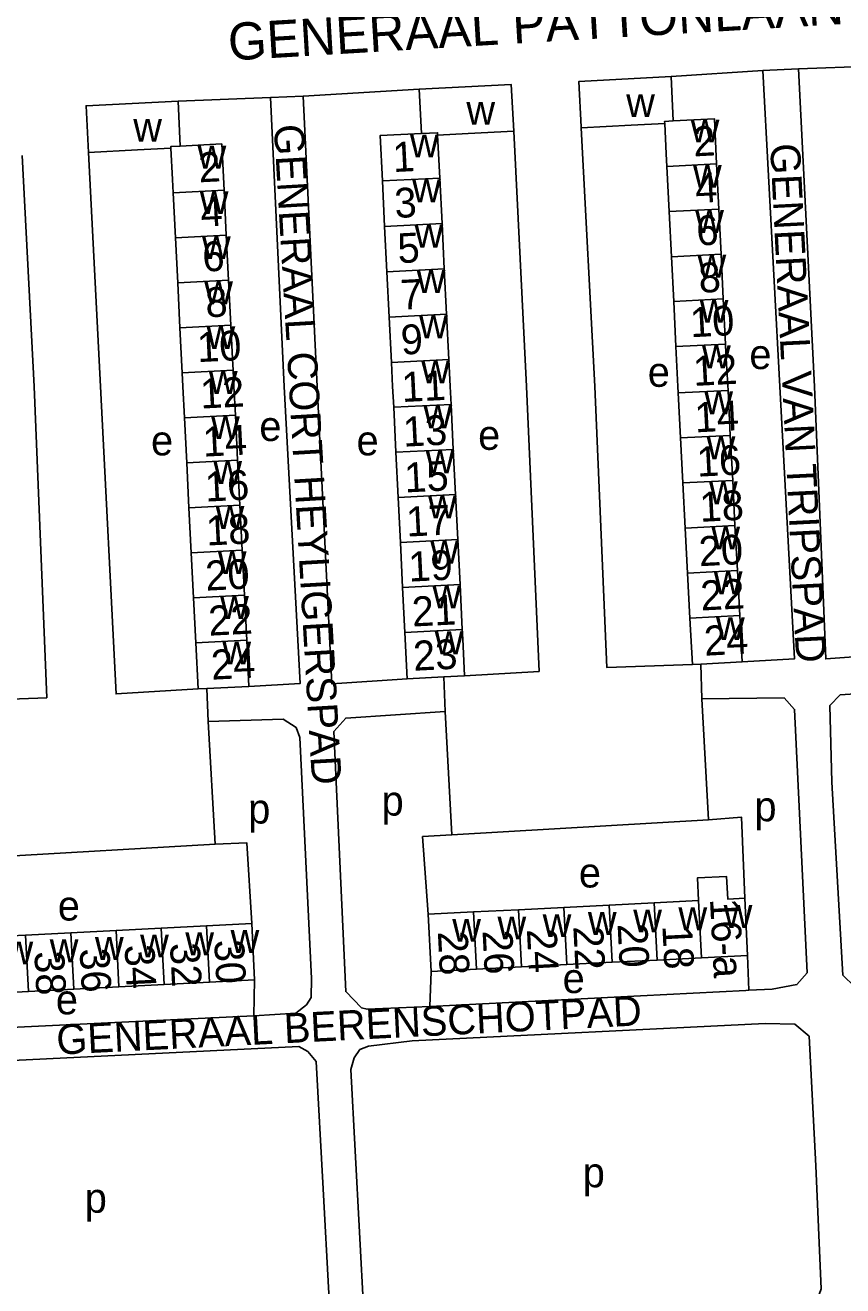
# Model space of a CAD drawing. Extents: x 159294 to 161936, y 384538 to 386517.
# Drawn here: x 161388.8 to 161498.7, y 385579.2 to 385748.5 of the extents above; entities that cross this region are included whole.
import ezdxf

# ---------------------------------------------------------------- set-up
doc = ezdxf.new("R2010")
doc.units = 0
for name, color, linetype in [('BLT_Basislijn', 7, 'Continuous'), ('BLT_Bebouwing', 7, 'Continuous'), ('BLT_Centroide', 7, 'Continuous'), ('BLT_Huisnummer', 7, 'Continuous'), ('BLT_Huisnummer_ tussenligend', 7, 'Continuous'), ('BLT_Huisnummer_reeks', 7, 'Continuous'), ('BLT_Onderverdeling_panden', 7, 'Continuous'), ('BLT_Straatnaam', 7, 'Continuous'), ('BLT_Straatnaam_verkleind', 7, 'Continuous')]:
    doc.layers.add(name, color=color, linetype=linetype)

msp = doc.modelspace()

# ---------------------------------------------------------------- linework, layer by layer
at = {"layer": 'BLT_Basislijn'}
for p, q in [((161475.6, 385741.64), (161487.92, 385742.47)), ((161487.92, 385742.47), (161492.75, 385742.69)), ((161508.06, 385743.25), (161492.75, 385742.69)), ((161409.33, 385738.32), (161421.78, 385738.84)), ((161426.15, 385739.02), (161421.78, 385738.84)), ((161426.15, 385739.02), (161441.74, 385739.94)), ((161479.59, 385662.72), (161479.74, 385658.06)), ((161445.23, 385656.36), (161445.06, 385660.98)), ((161413.19, 385659.43), (161413.4, 385654.98)), ((161480.63, 385641.78), (161479.74, 385658.06)), ((161446.14, 385639.77), (161445.23, 385656.36)), ((161413.4, 385654.98), (161414.31, 385638.51)), ((161480.63, 385641.78), (161446.14, 385639.77)), ((161414.31, 385638.51), (161380.08, 385636.52)), ((161486.08, 385618.9), (161485.9, 385623.58)), ((161419.53, 385615.47), (161419.62, 385620.28)), ((161443.18, 385616.7), (161443.35, 385621.41)), ((161377.03, 385613.45), (161419.53, 385615.47))]:
    msp.add_line(p, q, dxfattribs=at)
for points in [[(161485.15, 385663.01), (161492.21, 385663.42), (161490.21, 385700), (161487.92, 385742.47)], [(161506.47, 385664.15), (161496.4, 385663.41), (161494.88, 385700), (161492.75, 385742.69)], [(161418.87, 385659.71), (161425.77, 385660.11), (161423.59, 385700), (161421.78, 385738.84)], [(161440.13, 385660.74), (161430.01, 385660.06), (161428.03, 385700), (161426.15, 385739.02)], [(161454.45, 385734.29), (161456.16, 385700), (161457.86, 385661.73), (161447.85, 385661.12)], [(161478.47, 385662.66), (161466.97, 385662.26), (161465.37, 385700), (161463.53, 385734.75)], [(161388.36, 385731.02), (161389.99, 385700), (161391.68, 385658.18), (161381.85, 385657.81)], [(161412.02, 385659.37), (161401, 385658.7), (161398.91, 385700), (161397.29, 385731.45)], [(161511.65, 385659.49), (161498.34, 385658.6), (161496.96, 385657.17), (161497.23, 385646.85), (161498.69, 385620.93), (161500.25, 385619.42), (161509.83, 385619.75)], [(161486.08, 385618.9), (161489.18, 385619.04), (161492.52, 385619.67), (161493.89, 385621.26), (161492.2, 385656.63), (161490.8, 385658.16), (161479.74, 385658.06)], [(161443.18, 385616.7), (161434.74, 385616.34), (161434, 385616.54), (161431.87, 385618.72), (161430.28, 385653.64), (161431.87, 385655.45), (161445.23, 385656.36)], [(161419.53, 385615.47), (161425.18, 385615.83), (161426.59, 385616.95), (161427.21, 385617.93), (161427.29, 385620.46), (161425.7, 385652.86), (161425.2, 385654.18), (161423.45, 385655.33), (161413.4, 385654.98)], [(161480.63, 385641.78), (161485.09, 385642.14), (161485.51, 385631.27)], [(161446.14, 385639.77), (161442.21, 385639.55), (161442.95, 385629.1)], [(161414.31, 385638.51), (161418.58, 385638.68), (161419.23, 385627.86)], [(161443.18, 385616.7), (161485.67, 385618.88), (161486.08, 385618.9)], [(161495.05, 385595.31), (161494.15, 385612.73), (161492.26, 385614.34), (161488.24, 385614.45), (161440.82, 385612.09), (161434.95, 385611.37), (161433.78, 385610.93), (161432.99, 385609.82), (161432.55, 385608.26), (161434.3, 385575.49), (161434.94, 385574.37), (161436.21, 385573.48), (161493.97, 385576.39), (161495.52, 385578.01), (161495.8, 385578.78), (161495.05, 385595.31)], [(161428.83, 385592.2), (161427.9, 385609.34), (161426.77, 385610.66), (161425.58, 385611.32), (161369.6, 385608.62), (161367.69, 385607.65), (161366.84, 385606.32), (161366.55, 385602.63), (161368.13, 385572.42), (161369.7, 385570.54), (161370.4, 385570.36), (161426.69, 385573.21), (161427.74, 385573.5), (161429.49, 385575.37), (161429.6, 385578.17), (161428.83, 385592.2)]]:
    msp.add_lwpolyline(points, dxfattribs=at)
at = {"layer": 'BLT_Bebouwing'}
for p, q in [((161475.6, 385741.64), (161475.91, 385735.68)), ((161441.74, 385739.94), (161442.04, 385733.97)), ((161409.33, 385738.32), (161409.63, 385732.3)), ((161444.51, 385727.99), (161444.23, 385733.78)), ((161475.36, 385723.49), (161475.05, 385729.57)), ((161481.73, 385729.92), (161482.04, 385723.83)), ((161436.8, 385727.61), (161437.1, 385721.51)), ((161444.82, 385721.9), (161444.51, 385727.99)), ((161415.52, 385726.36), (161415.82, 385720.32)), ((161482.04, 385723.83), (161482.34, 385717.79)), ((161445.12, 385715.81), (161444.82, 385721.9)), ((161475.66, 385717.44), (161475.36, 385723.49)), ((161415.82, 385720.32), (161416.12, 385714.27)), ((161437.1, 385721.51), (161437.41, 385715.42)), ((161409.29, 385713.93), (161408.98, 385719.97)), ((161475.96, 385711.44), (161475.66, 385717.44)), ((161482.34, 385717.79), (161482.63, 385711.79)), ((161437.41, 385715.42), (161437.71, 385709.33)), ((161445.43, 385709.71), (161445.12, 385715.81)), ((161409.59, 385707.88), (161409.29, 385713.93)), ((161416.12, 385714.27), (161416.43, 385708.23)), ((161482.63, 385711.79), (161482.93, 385705.71)), ((161476.26, 385705.36), (161475.96, 385711.44)), ((161437.71, 385709.33), (161438.02, 385703.24)), ((161445.73, 385703.62), (161445.43, 385709.71)), ((161409.9, 385701.84), (161409.59, 385707.88)), ((161476.89, 385693.09), (161476.57, 385699.14)), ((161483.26, 385699.48), (161483.57, 385693.43)), ((161438.32, 385697.22), (161438.62, 385691.17)), ((161446.33, 385691.55), (161446.03, 385697.6)), ((161410.5, 385689.75), (161410.2, 385695.8)), ((161417.04, 385696.14), (161417.34, 385690.1)), ((161477.2, 385687.04), (161476.89, 385693.09)), ((161483.57, 385693.43), (161483.89, 385687.38)), ((161446.63, 385685.5), (161446.33, 385691.55)), ((161410.8, 385683.71), (161410.5, 385689.75)), ((161417.34, 385690.1), (161417.65, 385684.06)), ((161438.62, 385691.17), (161438.92, 385685.11)), ((161477.52, 385680.99), (161477.2, 385687.04)), ((161483.89, 385687.38), (161484.2, 385681.33)), ((161438.92, 385685.11), (161439.22, 385679.06)), ((161446.93, 385679.45), (161446.63, 385685.5)), ((161411.1, 385677.67), (161410.8, 385683.71)), ((161417.65, 385684.06), (161417.95, 385678.01)), ((161484.2, 385681.33), (161484.52, 385675.28)), ((161477.83, 385674.94), (161477.52, 385680.99)), ((161417.95, 385678.01), (161418.26, 385671.97)), ((161439.22, 385679.06), (161439.52, 385673.01)), ((161447.24, 385673.4), (161446.93, 385679.45)), ((161411.4, 385671.62), (161411.1, 385677.67)), ((161478.14, 385668.89), (161477.83, 385674.94)), ((161484.52, 385675.28), (161484.83, 385669.23)), ((161439.52, 385673.01), (161439.82, 385666.96)), ((161447.54, 385667.34), (161447.24, 385673.4)), ((161411.71, 385665.58), (161411.4, 385671.62)), ((161418.26, 385671.97), (161418.56, 385665.93)), ((161478.47, 385662.66), (161478.14, 385668.89)), ((161484.83, 385669.23), (161485.15, 385663.01)), ((161418.56, 385665.93), (161418.87, 385659.71)), ((161439.82, 385666.96), (161440.13, 385660.74)), ((161412.02, 385659.37), (161411.71, 385665.58)), ((161479.59, 385662.72), (161478.47, 385662.66)), ((161485.15, 385663.01), (161479.59, 385662.72)), ((161440.13, 385660.74), (161445.06, 385660.98)), ((161445.06, 385660.98), (161447.85, 385661.12)), ((161413.19, 385659.43), (161412.02, 385659.37)), ((161418.87, 385659.71), (161413.19, 385659.43)), ((161473.35, 385630.65), (161467.27, 385630.34)), ((161479.31, 385630.95), (161473.35, 385630.65)), ((161485.9, 385623.58), (161485.51, 385631.27)), ((161449.03, 385629.41), (161442.95, 385629.1)), ((161442.95, 385629.1), (161443.35, 385621.41)), ((161455.11, 385629.72), (161449.03, 385629.41)), ((161461.19, 385630.03), (161455.11, 385629.72)), ((161467.27, 385630.34), (161461.19, 385630.03)), ((161407.08, 385627.24), (161401, 385626.93)), ((161413.16, 385627.55), (161407.08, 385627.24)), ((161419.23, 385627.86), (161413.16, 385627.55)), ((161419.62, 385620.28), (161419.23, 385627.86)), ((161388.85, 385626.3), (161382.77, 385625.99)), ((161394.93, 385626.61), (161388.85, 385626.3)), ((161401, 385626.93), (161394.93, 385626.61)), ((161449.43, 385621.72), (161455.51, 385622.03)), ((161455.51, 385622.03), (161461.59, 385622.34)), ((161461.59, 385622.34), (161467.67, 385622.65)), ((161467.67, 385622.65), (161473.74, 385622.96)), ((161473.74, 385622.96), (161479.7, 385623.27)), ((161479.7, 385623.27), (161485.9, 385623.58)), ((161413.55, 385619.97), (161419.62, 385620.28)), ((161443.35, 385621.41), (161449.43, 385621.72)), ((161383.16, 385618.41), (161389.24, 385618.72)), ((161389.24, 385618.72), (161395.31, 385619.03)), ((161395.31, 385619.03), (161401.39, 385619.35)), ((161401.39, 385619.35), (161407.47, 385619.66)), ((161407.47, 385619.66), (161413.55, 385619.97))]:
    msp.add_line(p, q, dxfattribs=at)
for points in [[(161454.45, 385734.29), (161454.13, 385740.56), (161441.74, 385739.94)], [(161463.53, 385734.75), (161463.52, 385734.89), (161463.21, 385740.99), (161475.6, 385741.64)], [(161397.29, 385731.45), (161396.98, 385737.71), (161409.33, 385738.32)], [(161475.91, 385735.68), (161481.43, 385735.96), (161481.73, 385729.92)], [(161442.04, 385733.97), (161436.49, 385733.7), (161436.8, 385727.61)], [(161444.23, 385733.78), (161448.34, 385733.98), (161454.45, 385734.29)], [(161474.76, 385735.33), (161470.23, 385735.1), (161463.53, 385734.75)], [(161475.05, 385729.57), (161474.97, 385731.27), (161474.76, 385735.33)], [(161408.37, 385732.01), (161403.87, 385731.78), (161397.29, 385731.45)], [(161408.67, 385726.01), (161408.58, 385727.8), (161408.37, 385732.01)], [(161409.63, 385732.3), (161415.21, 385732.58), (161415.52, 385726.36)], [(161408.98, 385719.97), (161408.67, 385726.01)], [(161416.43, 385708.23), (161416.65, 385703.74), (161416.73, 385702.19)], [(161476.57, 385699.14), (161476.53, 385700), (161476.26, 385705.36)], [(161482.93, 385705.71), (161482.99, 385704.49), (161483.26, 385699.48)], [(161438.02, 385703.24), (161438.18, 385700), (161438.32, 385697.22)], [(161446.03, 385697.6), (161445.91, 385700), (161445.73, 385703.62)], [(161410.2, 385695.8), (161409.99, 385700), (161409.9, 385701.84)], [(161416.73, 385702.19), (161416.85, 385700), (161417.04, 385696.14)], [(161447.85, 385661.12), (161447.6, 385666.11), (161447.54, 385667.34)], [(161485.51, 385631.27), (161483.22, 385631.15), (161483.06, 385634.17), (161479.15, 385633.98), (161479.31, 385630.95)]]:
    msp.add_lwpolyline(points, dxfattribs=at)
at = {"layer": 'BLT_Onderverdeling_panden'}
for p, q in [((161481.73, 385729.92), (161475.05, 385729.57)), ((161444.51, 385727.99), (161436.8, 385727.61)), ((161415.52, 385726.36), (161408.67, 385726.01)), ((161482.04, 385723.83), (161475.36, 385723.49)), ((161444.82, 385721.9), (161437.1, 385721.51)), ((161415.82, 385720.32), (161408.98, 385719.97)), ((161482.34, 385717.79), (161475.66, 385717.44)), ((161445.12, 385715.81), (161437.41, 385715.42)), ((161416.12, 385714.27), (161409.29, 385713.93)), ((161482.63, 385711.79), (161475.96, 385711.44)), ((161445.43, 385709.71), (161437.71, 385709.33)), ((161416.43, 385708.23), (161409.59, 385707.88)), ((161482.93, 385705.71), (161476.26, 385705.36)), ((161445.73, 385703.62), (161438.02, 385703.24)), ((161416.73, 385702.19), (161409.9, 385701.84)), ((161476.57, 385699.14), (161483.26, 385699.48)), ((161438.32, 385697.22), (161446.03, 385697.6)), ((161410.2, 385695.8), (161417.04, 385696.14)), ((161476.89, 385693.09), (161483.57, 385693.43)), ((161438.62, 385691.17), (161446.33, 385691.55)), ((161410.5, 385689.75), (161417.34, 385690.1)), ((161477.2, 385687.04), (161483.89, 385687.38)), ((161438.92, 385685.11), (161446.63, 385685.5)), ((161410.8, 385683.71), (161417.65, 385684.06)), ((161477.52, 385680.99), (161484.2, 385681.33)), ((161411.1, 385677.67), (161417.95, 385678.01)), ((161439.22, 385679.06), (161446.93, 385679.45)), ((161477.83, 385674.94), (161484.52, 385675.28)), ((161439.52, 385673.01), (161447.24, 385673.4)), ((161411.4, 385671.62), (161418.26, 385671.97)), ((161478.14, 385668.89), (161484.83, 385669.23)), ((161411.71, 385665.58), (161418.56, 385665.93)), ((161439.82, 385666.96), (161447.54, 385667.34)), ((161473.74, 385622.96), (161473.35, 385630.65)), ((161479.7, 385623.27), (161479.31, 385630.95)), ((161449.43, 385621.72), (161449.03, 385629.41)), ((161455.51, 385622.03), (161455.11, 385629.72)), ((161461.59, 385622.34), (161461.19, 385630.03)), ((161467.67, 385622.65), (161467.27, 385630.34)), ((161407.47, 385619.66), (161407.08, 385627.24)), ((161413.55, 385619.97), (161413.16, 385627.55)), ((161389.24, 385618.72), (161388.85, 385626.3)), ((161395.31, 385619.03), (161394.93, 385626.61)), ((161401.39, 385619.35), (161401, 385626.93))]:
    msp.add_line(p, q, dxfattribs=at)
for points in [[(161474.76, 385735.33), (161474.74, 385735.61), (161475.91, 385735.68)], [(161442.04, 385733.97), (161444.21, 385734.08), (161444.23, 385733.78)], [(161408.37, 385732.01), (161408.36, 385732.24), (161409.63, 385732.3)]]:
    msp.add_lwpolyline(points, dxfattribs=at)

# ---------------------------------------------------------------- texts
at = {"layer": 'BLT_Centroide'}
for s, p in [('w', (161469.57, 385736.19)), ('w', (161448.09, 385735.16)), ('w', (161403.31, 385732.88)), ('w', (161478.24, 385732.78)), ('w', (161440.51, 385730.78)), ('w', (161411.95, 385729.28)), ('w', (161478.55, 385726.69)), ('w', (161440.8, 385724.75)), ('w', (161412.25, 385723.16)), ('w', (161478.84, 385720.62)), ('w', (161412.55, 385717.12)), ('w', (161441.12, 385718.66)), ('w', (161479.15, 385714.62)), ('w', (161441.41, 385712.56)), ('w', (161412.85, 385711.06)), ('w', (161479.45, 385708.56)), ('w', (161441.73, 385706.47)), ('w', (161413.16, 385705.03)), ('w', (161479.76, 385702.44)), ('e', (161486.13, 385702.34)), ('w', (161442.02, 385700.41)), ('w', (161413.47, 385699)), ('e', (161472.47, 385699.96)), ('w', (161480.07, 385696.28)), ('w', (161442.32, 385694.38)), ('w', (161413.77, 385692.94)), ('e', (161420.26, 385692.68)), ('e', (161405.7, 385690.75)), ('e', (161433.33, 385690.75)), ('e', (161449.67, 385691.49)), ('w', (161480.38, 385690.22)), ('w', (161442.62, 385688.34)), ('w', (161414.07, 385686.91)), ('w', (161480.7, 385684.19)), ('w', (161442.93, 385682.28)), ('w', (161414.38, 385680.88)), ('w', (161481.02, 385678.12)), ('w', (161414.68, 385674.81)), ('w', (161443.23, 385676.22)), ('w', (161481.34, 385672.09)), ('w', (161443.52, 385670.19)), ('w', (161414.98, 385668.78)), ('w', (161481.65, 385665.94)), ('w', (161443.84, 385664.03)), ('w', (161415.29, 385662.66)), ('p', (161418.76, 385641.29)), ('p', (161436.69, 385642.36)), ('p', (161486.81, 385641.6)), ('e', (161463.21, 385632.7)), ('e', (161393.17, 385628.26)), ('w', (161452.27, 385625.72)), ('w', (161458.34, 385626.03)), ('w', (161464.42, 385626.34)), ('w', (161470.52, 385626.66)), ('w', (161476.59, 385626.95)), ('w', (161482.67, 385627.27)), ('w', (161416.39, 385623.92)), ('w', (161446.19, 385625.41)), ('w', (161386, 385622.36)), ('w', (161392.08, 385622.67)), ('w', (161398.16, 385622.98)), ('w', (161404.23, 385623.3)), ('w', (161410.31, 385623.61)), ('e', (161461.03, 385618.52)), ('e', (161392.91, 385615.66)), ('p', (161463.73, 385592.43)), ('p', (161396.79, 385589.01))]:
    msp.add_text(s, height=4, dxfattribs=at).set_placement(p)
at = {"layer": 'BLT_Huisnummer'}
for s, rotation, p in [('2', 2.9788, (161478.67, 385730.9)), ('1', 2.8568, (161438.27, 385728.8)), ('2', 2.8441, (161412.17, 385727.42)), ('6', 2.9788, (161479.1, 385718.92)), ('5', 2.8568, (161438.93, 385716.56)), ('6', 2.8441, (161412.69, 385715.42)), ('10', 2.9788, (161478.26, 385706.61)), ('9', 2.8568, (161439.37, 385704.27)), ('10', 2.8441, (161411.99, 385703.27)), ('14', 2.9788, (161478.86, 385693.83)), ('14', 2.8441, (161412.75, 385690.57)), ('13', 2.8568, (161439.65, 385691.91)), ('18', 2.9788, (161479.53, 385681.81)), ('18', 2.8441, (161413.19, 385678.63)), ('17', 2.8568, (161440.09, 385679.83)), ('24', 2.9788, (161480.13, 385663.83)), ('23', 2.8568, (161441.03, 385661.81)), ('24', 2.8441, (161413.86, 385660.61)), ('20', 272.9141, (161468.41, 385627.78)), ('30', 272.9382, (161414.19, 385625.6)), ('28', 272.9141, (161444.25, 385626.76)), ('24', 272.9141, (161456.22, 385627.08)), ('38', 272.9382, (161390.01, 385624.08)), ('34', 272.9382, (161402.14, 385624.95))]:
    msp.add_text(s, height=4, rotation=rotation, dxfattribs=at).set_placement(p)
at = {"layer": 'BLT_Huisnummer_ tussenligend'}
for s, rotation, p in [('4', 2.9788, (161478.95, 385724.65)), ('4', 2.8441, (161412.45, 385721.47)), ('3', 2.8568, (161438.52, 385722.63)), ('8', 2.9788, (161479.41, 385712.58)), ('8', 2.8441, (161413.1, 385709.28)), ('7', 2.8568, (161439.32, 385710.32)), ('12', 2.9788, (161478.67, 385700.07)), ('11', 2.8568, (161439.47, 385697.91)), ('12', 2.8441, (161412.4, 385697.03)), ('16', 2.9788, (161479.16, 385687.88)), ('15', 2.8568, (161439.85, 385685.76)), ('16', 2.8441, (161413.05, 385684.53)), ('20', 2.9788, (161479.43, 385675.85)), ('19', 2.8568, (161440.4, 385673.78)), ('20', 2.8441, (161413.09, 385672.57)), ('22', 2.9788, (161479.65, 385669.9)), ('21', 2.8568, (161440.86, 385667.75)), ('22', 2.8441, (161413.5, 385666.52)), ('22', 272.9141, (161462.46, 385627.46)), ('18', 272.9141, (161474.43, 385627.56)), ('26', 272.9141, (161450.26, 385626.88)), ('36', 272.9382, (161396.1, 385624.45)), ('32', 272.9382, (161408.24, 385625.19))]:
    msp.add_text(s, height=4, rotation=rotation, dxfattribs=at).set_placement(p)
at = {"layer": 'BLT_Huisnummer_reeks'}
msp.add_text('16-a', height=4, rotation=272.9141, dxfattribs=at).set_placement((161480.83, 385631.17))
at = {"layer": 'BLT_Straatnaam'}
msp.add_text('GENERAAL PATTONLAAN', height=5, rotation=3.407, dxfattribs=at).set_placement((161416.2, 385743.78))
at = {"layer": 'BLT_Straatnaam_verkleind'}
for s, rotation, p in [('GENERAAL CORT HEYLIGERSPAD', 273.3229, (161422.21, 385735.13)), ('GENERAAL VAN TRIPSPAD', 272.8907, (161488.92, 385732.57)), ('GENERAAL BERENSCHOTPAD', 2.8775, (161393.08, 385610.24))]:
    msp.add_text(s, height=4, rotation=rotation, dxfattribs=at).set_placement(p)

doc.saveas('drawing.dxf')
